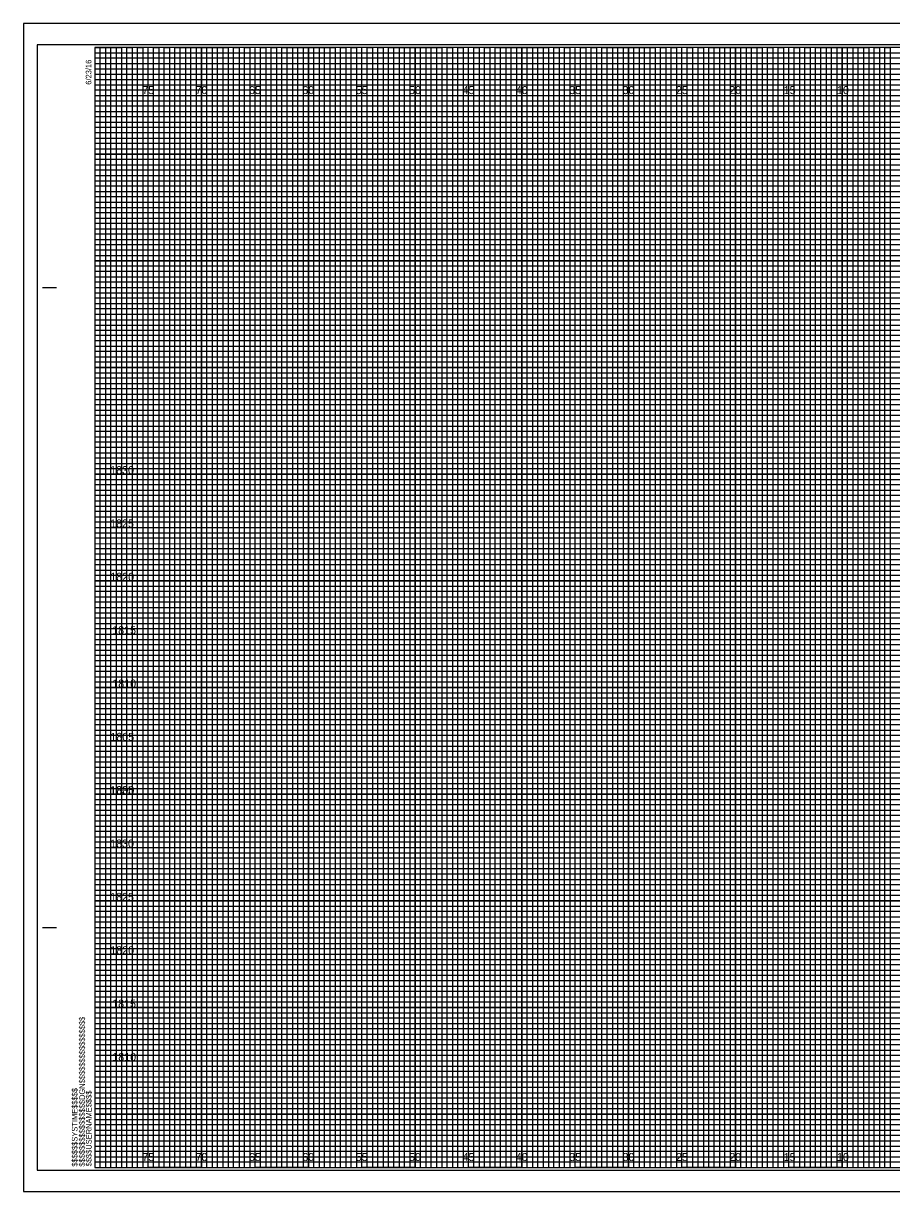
# Model space of a CAD drawing. Extents: x -7 to 162, y -2 to 767.
# Drawn here: x -6.7 to 74.6, y -2.3 to 107.3 of the extents above; entities that cross this region are included whole.
import ezdxf

# ---------------------------------------------------------------- set-up
doc = ezdxf.new("R2010")
doc.units = 0
for name, color, linetype in [('Prop Grid Mask', 7, 'Continuous'), ('Prop XS Elevation Labels', 7, 'Continuous'), ('Sheet Cross Section CELL', 7, 'Continuous'), ('Sheet Cross Section Grid Major CELL', 7, 'Continuous'), ('Sheet Cross Section Grid Middle CELL', 7, 'Continuous'), ('Sheet Cross Section Grid Minor 1 CELL', 7, 'Continuous'), ('Sheet Cross Section Grid Minor 2 CELL', 7, 'Continuous'), ('Sheet Cutting Line CELL', 7, 'Continuous'), ('Sheet DOT Grid CELL', 7, 'Continuous'), ('Sheet Plot Border Inside CELL', 7, 'Continuous'), ('Sheet Plot Border Outside CELL', 7, 'Continuous')]:
    doc.layers.add(name, color=color, linetype=linetype)

msp = doc.modelspace()

# ---------------------------------------------------------------- linework, layer by layer
at = {"layer": 'Sheet Cross Section CELL'}
for p, q in [((-4.9, 82.5), (-3.65, 82.5)), ((-4.85, 82.5), (-3.6, 82.5)), ((-4.9, 22.5), (-3.65, 22.5)), ((-4.85, 22.5), (-3.6, 22.5)), ((0, 0), (0, 0)), ((0, 0), (0, 0)), ((0, 0), (0, 0)), ((0, 0), (0, 0)), ((0, 0), (0, 0)), ((0, 0), (0, 0)), ((0, 0), (0, 0))]:
    msp.add_line(p, q, dxfattribs=at)
msp.add_lwpolyline([(160, 105), (0, 105), (0, 0), (160, 0)], close=True, dxfattribs=at)
at = {"layer": 'Sheet Cross Section Grid Major CELL'}
for p, q in [((5, 105), (0, 105)), ((5, 0), (5, 105)), ((15, 105), (10, 105)), ((10, 105), (10, 0)), ((15, 0), (15, 105)), ((25, 105), (20, 105)), ((20, 105), (20, 0)), ((25, 0), (25, 105)), ((35, 105), (30, 105)), ((30, 105), (30, 0)), ((35, 0), (35, 105)), ((45, 105), (40, 105)), ((40, 105), (40, 0)), ((45, 0), (45, 105)), ((55, 105), (50, 105)), ((50, 105), (50, 0)), ((55, 0), (55, 105)), ((65, 105), (60, 105)), ((60, 105), (60, 0)), ((65, 0), (65, 105)), ((75, 105), (70, 105)), ((70, 105), (70, 0)), ((10, 0), (5, 0)), ((20, 0), (15, 0)), ((30, 0), (25, 0)), ((40, 0), (35, 0)), ((50, 0), (45, 0)), ((60, 0), (55, 0)), ((70, 0), (65, 0))]:
    msp.add_line(p, q, dxfattribs=at)
for points in [[(0, 100), (160, 100), (160, 95), (0, 95)], [(0, 90), (160, 90), (160, 85), (0, 85)], [(0, 80), (160, 80), (160, 75), (0, 75)], [(0, 70), (160, 70), (160, 65), (0, 65)], [(0, 60), (160, 60), (160, 55), (0, 55)], [(0, 50), (160, 50), (160, 45), (0, 45)], [(0, 40), (160, 40), (160, 35), (0, 35)], [(0, 30), (160, 30), (160, 25), (0, 25)], [(0, 20), (160, 20), (160, 15), (0, 15)], [(0, 10), (160, 10), (160, 5), (0, 5)]]:
    msp.add_lwpolyline(points, dxfattribs=at)
at = {"layer": 'Sheet Cross Section Grid Middle CELL'}
for points in [[(0, 105), (2.5, 105), (2.5, 0), (7.5, 0), (7.5, 105), (12.5, 105), (12.5, 0), (17.5, 0), (17.5, 105), (22.5, 105), (22.5, 0), (27.5, 0), (27.5, 105), (32.5, 105), (32.5, 0), (37.5, 0), (37.5, 105), (42.5, 105), (42.5, 0), (47.5, 0), (47.5, 105), (52.5, 105), (52.5, 0), (57.5, 0), (57.5, 105), (62.5, 105), (62.5, 0), (67.5, 0), (67.5, 105), (72.5, 105), (72.5, 0), (77.5, 0)], [(0, 102.5), (137.5, 102.5)], [(0, 92.5), (160, 92.5), (160, 97.5), (0, 97.5)], [(0, 82.5), (160, 82.5), (160, 87.5), (0, 87.5)], [(0, 72.5), (160, 72.5), (160, 77.5), (0, 77.5)], [(0, 62.5), (160, 62.5), (160, 67.5), (0, 67.5)], [(0, 52.5), (160, 52.5), (160, 57.5), (0, 57.5)], [(0, 42.5), (160, 42.5), (160, 47.5), (0, 47.5)], [(0, 32.5), (160, 32.5), (160, 37.5), (0, 37.5)], [(0, 22.5), (160, 22.5), (160, 27.5), (0, 27.5)], [(0, 12.5), (160, 12.5), (160, 17.5), (0, 17.5)], [(0, 2.5), (160, 2.5), (160, 7.5), (0, 7.5)]]:
    msp.add_lwpolyline(points, dxfattribs=at)
at = {"layer": 'Sheet Cross Section Grid Minor 1 CELL'}
for p, q in [((0, 104.5), (130, 104.5)), ((130, 103.99), (0, 103.99)), ((0, 103.99), (0, 103.5)), ((0, 103.5), (130, 103.5)), ((130, 102.95), (0, 102.95)), ((0, 102.95), (0, 102)), ((0, 102), (160, 102))]:
    msp.add_line(p, q, dxfattribs=at)
for points in [[(0, 101.5), (135, 101.5), (160, 101.5), (160, 101), (0, 101)], [(0, 100.5), (160, 100.5), (160, 99.5), (0, 99.5)], [(0, 99), (160, 99), (160, 98.5), (0, 98.49)], [(0, 98), (160, 98), (160, 97), (0, 97)], [(0, 96.5), (160, 96.5), (160, 96), (0, 96)], [(0, 95.5), (160, 95.5), (160, 94.5), (0, 94.5)], [(0, 94), (160, 94), (160, 93.5), (0, 93.5)], [(0, 93), (160, 93), (160, 92), (0, 92)], [(0, 91.5), (160, 91.5), (160, 91), (0, 91)], [(0, 90.5), (160, 90.5), (160, 89.5), (0, 89.5)], [(0, 89), (160, 89), (160, 88.5), (0, 88.5)], [(0, 88), (160, 88), (160, 86.98), (160, 86.5), (160, 86), (0, 86)], [(0, 87), (160, 87), (160, 86.5), (0, 86.5)], [(0, 85.5), (160, 85.5), (160, 84.5), (0, 84.52)], [(0, 84.52), (160, 84.5), (160, 84), (0, 84)], [(0, 83.5), (160, 83.5), (160, 83), (0, 83)], [(0, 82), (160, 82), (160, 81.5), (0, 81.5)], [(0, 81), (160, 81), (160, 80.5), (0, 80.5)], [(-0.04, 79.45), (160, 79.45), (160, 78.94), (-0.04, 78.94)], [(0, 78.5), (160, 78.5), (160, 78), (0, 78)], [(0, 77), (160, 77), (160, 76.5), (0, 76.5)], [(0, 76), (160, 76), (160, 75.5), (0, 75.5)], [(0, 74.5), (160, 74.5), (160, 74), (0, 74)], [(0, 73.5), (160, 73.5), (160, 73), (0, 73)], [(0, 72), (160, 72), (160, 71.5), (0, 71.5)], [(0, 71), (160, 71), (160, 70.5), (0, 70.5)], [(0, 69.5), (160, 69.5), (160, 68.99), (0, 69)], [(0, 68.5), (160, 68.5), (160, 68), (0, 68)], [(0, 67), (160, 67), (160, 66.5), (0, 66.5)], [(0, 66), (160, 66), (160, 65.5), (0, 65.5)], [(0, 64.5), (160, 64.5), (160, 64), (0, 64)], [(0, 63.5), (160, 63.5), (160, 63), (0, 63)], [(0, 62), (160, 62), (160, 61.5), (0, 61.5)], [(0, 61), (160, 61), (160, 60.5), (0, 60.5)], [(0, 59.5), (160, 59.5), (160, 59), (0, 59)], [(0, 58.5), (160.03, 58.45), (160, 58), (0, 58)], [(0, 57), (160, 57), (160, 56.5), (0, 56.5)], [(0, 56), (160, 56), (160, 55.5), (0, 55.5)], [(0, 54.5), (160, 54.5), (160, 54), (0, 54)], [(0, 53.5), (160, 53.5), (160, 53), (0, 53)], [(0, 52), (160, 52), (160, 51.5), (0, 51.5)], [(0, 51), (160, 51), (160, 50.5), (0, 50.5)], [(0, 49.5), (160, 49.5), (160, 49), (0, 49)], [(0, 48.5), (160, 48.5), (160, 48), (0, 48)], [(0, 47), (160, 47), (160, 46.5), (0, 46.5)], [(0, 46), (160, 46), (160, 45.5), (0, 45.5)], [(0, 44.5), (160, 44.5), (160, 44), (0, 44)], [(0, 43.5), (160, 43.5), (160, 43), (0, 43)], [(0, 42), (160, 42), (160, 41.5), (0, 41.5)], [(0, 41), (160, 41), (160, 40.5), (0, 40.5)], [(0, 39.5), (160, 39.5), (160, 38.99), (0, 39)], [(0, 38.5), (160, 38.5), (160, 38), (0, 38)], [(0, 37), (160, 37), (160, 36.5), (0, 36.5)], [(0, 36), (160, 36), (160, 35.5), (0, 35.5)], [(0, 34.5), (160, 34.5), (160, 34), (0, 34)], [(0, 33.5), (160, 33.5), (160, 33), (0, 33)], [(0, 32), (160, 32), (160, 31.5), (0, 31.5)], [(0, 31), (160, 31), (160, 30.5), (0, 30.5)], [(0, 29.5), (160, 29.5), (160, 29), (0, 29)], [(0, 28.5), (160.03, 28.46), (160, 28), (0, 28)], [(0, 27), (160, 27), (160, 26.5), (0, 26.5)], [(0, 26), (160, 26), (160, 25.5), (0, 25.5)], [(0, 24.5), (160, 24.5), (160, 24), (0, 24)], [(0, 23.5), (160, 23.5), (160, 23), (0, 23)], [(0, 22), (160, 22), (160, 21.5), (0, 21.5)], [(0, 21), (160, 21), (160, 20.5), (0, 20.5)], [(0, 19.5), (160, 19.5), (160, 19), (0, 19)], [(0, 18.5), (160, 18.5), (160, 18), (0, 18)], [(0, 17), (160, 17), (160, 16.5), (0, 16.5)], [(0, 16), (160, 16), (160, 15.5), (0, 15.5)], [(0, 14.5), (160, 14.5), (160, 14), (0, 14)], [(0, 13.5), (160, 13.5), (160, 13), (0, 13)], [(0, 12), (160, 12), (160, 11.5), (0, 11.5)], [(0, 11), (160, 11), (160, 10.5), (0, 10.5)], [(0, 9.5), (160, 9.5), (160, 9), (0, 9)], [(0, 8.5), (160, 8.5), (160, 8), (0, 8)], [(0, 7), (160, 7), (160, 6.5), (0, 6.5)], [(0, 6), (160, 6), (160, 5.5), (0, 5.5)], [(0, 4.5), (160, 4.5), (160, 4), (0, 4)], [(0, 3.5), (160, 3.5), (160, 3), (0, 3)], [(0, 2), (160, 2), (160, 1.5), (0, 1.5)], [(0, 1), (160, 1), (160, 0.5), (0, 0.5)]]:
    msp.add_lwpolyline(points, dxfattribs=at)
at = {"layer": 'Sheet Cross Section Grid Minor 2 CELL'}
for points in [[(0, 0), (0.5, 0), (0.5, 105), (1, 105), (1, 0)], [(1, 0), (1.5, 0), (1.5, 105), (2, 105), (2, 0)], [(2.5, 0), (3, 0), (3, 105), (3.5, 105), (3.5, 0)], [(3.5, 0), (4, 0), (4, 105), (4.5, 105), (4.5, 0)], [(5, 0), (5.5, 0), (5.5, 105), (6, 105), (6, 0)], [(6, 0), (6.5, 0), (6.5, 105), (7, 105), (7, 0)], [(7.5, 0), (8, 0), (8, 105), (8.5, 105), (8.5, 0)], [(8.5, 0), (9, 0), (9, 105), (9.5, 105), (9.5, 0)], [(10, 0), (10.5, 0), (10.5, 105), (11, 105), (11, 0)], [(11, 0), (11.5, 0), (11.5, 105), (12, 105), (12, 0)], [(12.5, 0), (13, 0), (13, 105), (13.5, 105), (13.5, 0)], [(13.5, 0), (14, 0), (14, 105), (14.5, 105), (14.5, 0)], [(15, 0), (15.5, 0), (15.5, 105), (16, 105), (16, 0)], [(16, 0), (16.5, 0), (16.5, 105), (17, 105), (17, 0)], [(17.5, 0), (18, 0), (18, 105), (18.5, 105), (18.5, 0)], [(18.5, 0), (19, 0), (19, 105), (19.5, 105), (19.5, 0)], [(20, 0), (20.5, 0), (20.5, 105), (21, 105), (21, 0)], [(21, 0), (21.5, 0), (21.5, 105), (22, 105), (22, 0)], [(22.5, 0), (23, 0), (23, 105), (23.5, 105), (23.5, 0)], [(23.5, 0), (24, 0), (24, 105), (24.5, 105), (24.5, 0)], [(25, 0), (25.5, 0), (25.5, 105), (26, 105), (26, 0)], [(26, 0), (26.5, 0), (26.5, 105), (27, 105), (27, 0)], [(27.5, 0), (28, 0), (28, 105), (28.5, 105), (28.5, 0)], [(28.5, 0), (29, 0), (29, 105), (29.5, 105), (29.5, 0)], [(30, 0), (30.5, 0), (30.5, 105), (31, 105), (31, 0)], [(31, 0), (31.5, 0), (31.5, 105), (32, 105), (32, 0)], [(32.5, 0), (33, 0), (33, 105), (33.5, 105), (33.5, 0)], [(33.5, 0), (34, 0), (34, 105), (34.5, 105), (34.5, 0)], [(35, 0), (35.5, 0), (35.5, 105), (36, 105), (36, 0)], [(36, 0), (36.5, 0), (36.5, 105), (37, 105), (37, 0)], [(37.5, 0), (38, 0), (38, 105), (38.5, 105), (38.5, 0)], [(38.5, 0), (39, 0), (39, 105), (39.5, 105), (39.5, 0)], [(40, 0), (40.5, 0), (40.5, 105), (41, 105), (41, 0)], [(41, 0), (41.5, 0), (41.5, 105), (42, 105), (42, 0)], [(42.5, 0), (43, 0), (43, 105), (43.5, 105), (43.5, 0)], [(43.5, 0), (44, 0), (44, 105), (44.5, 105), (44.5, 0)], [(45, 0), (45.5, 0), (45.5, 105), (46, 105), (46, 0)], [(46, 0), (46.5, 0), (46.5, 105), (47, 105), (47, 0)], [(47.5, 0), (48, 0), (48, 105), (48.5, 105), (48.5, 0)], [(48.5, 0), (49, 0), (49, 105), (49.5, 105), (49.5, 0)], [(50, 0), (50.5, 0), (50.5, 105), (51, 105), (51, 0)], [(51, 0), (51.5, 0), (51.5, 105), (52, 105), (52, 0)], [(52.5, 0), (53, 0), (53, 105), (53.5, 105), (53.5, 0)], [(53.5, 0), (54, 0), (54, 105), (54.5, 105), (54.5, 0)], [(55, 0), (55.5, 0), (55.5, 105), (56, 105), (56, 0)], [(56, 0), (56.5, 0), (56.5, 105), (57, 105), (57, 0)], [(57.5, 0), (58, 0), (58, 105), (58.5, 105), (58.5, 0)], [(58.5, 0), (59, 0), (59, 105), (59.5, 105), (59.5, 0)], [(60, 0), (60.5, 0), (60.5, 105), (61, 105), (61, 0)], [(61, 0), (61.5, 0), (61.5, 105), (62, 105), (62, 0)], [(62.5, 0), (63, 0), (63, 105), (63.5, 105), (63.5, 0)], [(63.5, 0), (64, 0), (64, 105), (64.5, 105), (64.5, 0)], [(65, 0), (65.5, 0), (65.5, 105), (66, 105), (66, 0)], [(66, 0), (66.5, 0), (66.5, 105), (67, 105), (67, 0)], [(67.5, 0), (68, 0), (68, 105), (68.5, 105), (68.5, 0)], [(68.5, 0), (69, 0), (69, 105), (69.5, 105), (69.5, 0)], [(70, 0), (70.5, 0), (70.5, 105), (71, 105), (71, 0)], [(71, 0), (71.5, 0), (71.5, 105), (72, 105), (72, 0)], [(72.5, 0), (73, 0), (73, 105), (73.5, 105), (73.5, 0)], [(73.5, 0), (74, 0), (74, 105), (74.5, 105), (74.5, 0)]]:
    msp.add_lwpolyline(points, dxfattribs=at)
at = {"layer": 'Sheet Cutting Line CELL'}
for p, q in [((161.65, 107.25), (-6.7, 107.25)), ((-6.7, 107.25), (-6.7, -2.25)), ((-6.7, -2.25), (161.65, -2.25))]:
    msp.add_line(p, q, dxfattribs=at)
at = {"layer": 'Sheet DOT Grid CELL'}
for p, q in [((5, 0), (5, 105)), ((10, 0), (10, 105)), ((15, 0), (15, 105)), ((20, 0), (20, 105)), ((25, 0), (25, 105)), ((30, 0), (30, 105)), ((35, 0), (35, 105)), ((40, 0), (40, 105)), ((45, 0), (45, 105)), ((50, 0), (50, 105)), ((55, 0), (55, 105)), ((60, 0), (60, 105)), ((65, 0), (65, 105)), ((70, 0), (70, 105)), ((0, 100), (160, 100)), ((0, 95), (160, 95)), ((0, 90), (160, 90)), ((0, 85), (160, 85)), ((0, 80), (160, 80)), ((0, 75), (160, 75)), ((0, 70), (160, 70)), ((0, 65), (160, 65)), ((0, 60), (160, 60)), ((0, 55), (160, 55)), ((0, 50), (160, 50)), ((0, 45), (160, 45)), ((0, 40), (160, 40)), ((0, 35), (160, 35)), ((0, 30), (160, 30)), ((0, 25), (160, 25)), ((0, 20), (160, 20)), ((0, 15), (160, 15)), ((0, 10), (160, 10)), ((0, 5), (160, 5))]:
    msp.add_line(p, q, dxfattribs=at)
at = {"layer": 'Sheet Plot Border Inside CELL'}
msp.add_lwpolyline([(-5.4, -0.25), (161.2, -0.25), (161.2, 105.25), (-5.4, 105.25)], close=True, dxfattribs=at)
at = {"layer": 'Sheet Plot Border Outside CELL'}
msp.add_lwpolyline([(-6.7, -2.25), (161.65, -2.25), (161.65, 107.25), (-6.7, 107.25)], close=True, dxfattribs=at)

# ---------------------------------------------------------------- texts
at = {"layer": 'Prop Grid Mask'}
for s, p in [('75', (4.44, 100.62)), ('70', (9.43, 100.62)), ('65', (14.44, 100.62)), ('60', (19.43, 100.62)), ('55', (24.44, 100.62)), ('50', (29.43, 100.62)), ('45', (34.44, 100.62)), ('40', (39.43, 100.62)), ('35', (44.44, 100.62)), ('30', (49.43, 100.62)), ('25', (54.44, 100.62)), ('20', (59.43, 100.62)), ('15', (64.53, 100.62)), ('10', (69.52, 100.62)), ('75', (4.44, 0.62)), ('70', (9.43, 0.62)), ('65', (14.44, 0.62)), ('60', (19.43, 0.62)), ('55', (24.44, 0.62)), ('50', (29.43, 0.62)), ('45', (34.44, 0.62)), ('40', (39.43, 0.62)), ('35', (44.44, 0.62)), ('30', (49.43, 0.62)), ('25', (54.44, 0.62)), ('20', (59.43, 0.62)), ('15', (64.53, 0.62)), ('10', (69.52, 0.62))]:
    msp.add_text(s, height=0.75, dxfattribs=at).set_placement(p)
at = {"layer": 'Prop XS Elevation Labels'}
for s, p in [('1830', (1.43, 65)), ('1825', (1.43, 60)), ('1820', (1.44, 55)), ('1815', (1.62, 50)), ('1810', (1.63, 45)), ('1805', (1.45, 40)), ('1835', (1.42, 35)), ('1800', (1.46, 35)), ('1830', (1.43, 30)), ('1825', (1.43, 25)), ('1820', (1.44, 20)), ('1815', (1.62, 15)), ('1810', (1.63, 10))]:
    msp.add_text(s, height=0.75, dxfattribs=at).set_placement(p)
at = {"layer": 'Sheet Cross Section CELL'}
for s, p in [('6/23/16', (-0.33, 101.5)), ('$$$$$$$$$$$$$$$$DGN$$$$$$$$$$$$$$$$', (-0.94, 0.09)), ('$$$$$$SYSTIME$$$$$', (-1.63, 0.09)), ('$$$$USERNAME$$$$', (-0.31, 0.12))]:
    msp.add_text(s, height=0.525, rotation=90, dxfattribs=at).set_placement(p)

doc.saveas('drawing.dxf')
